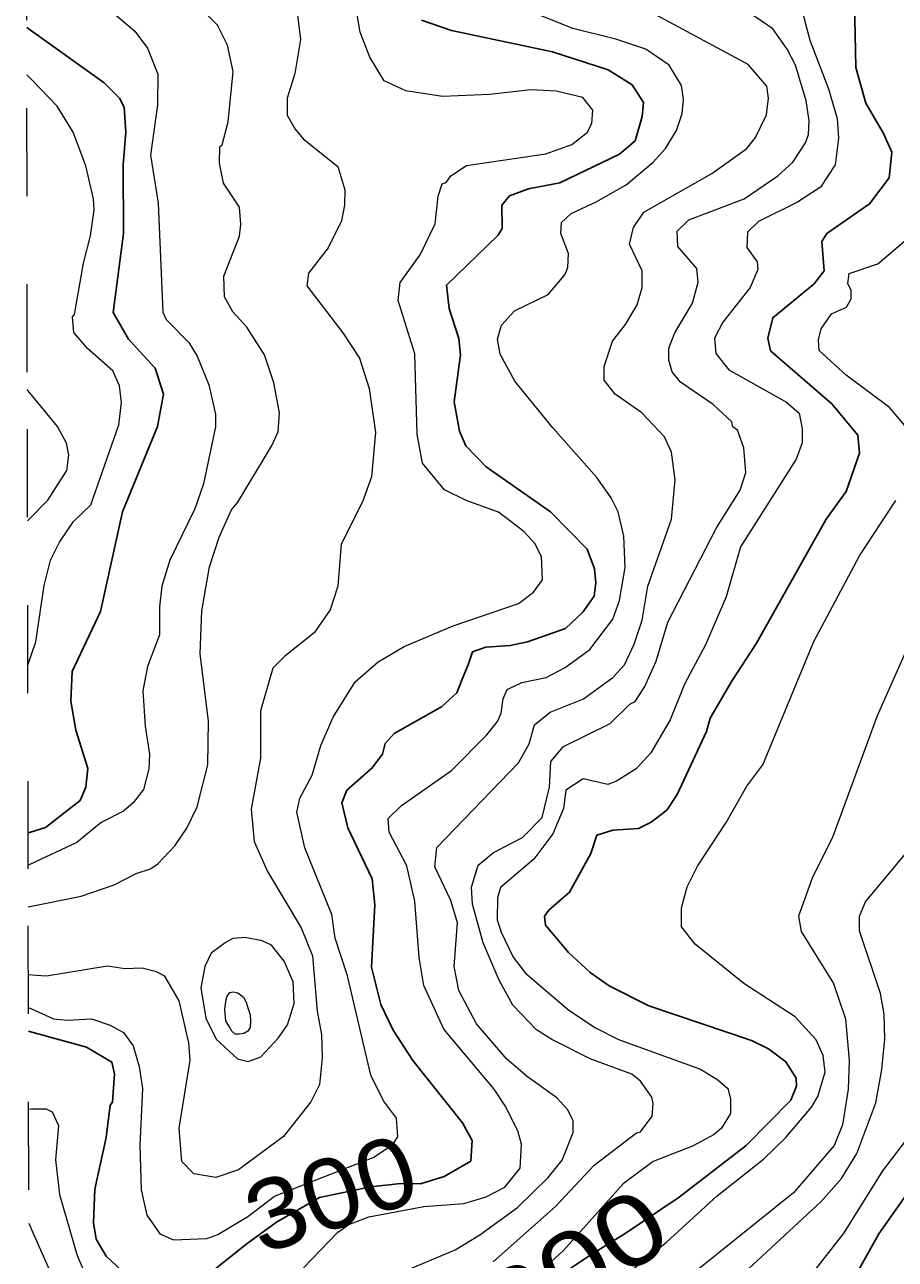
# Model space of a CAD drawing. Extents: x 474.5 to 500, y 7345.7 to 7373.4.
# Drawn here: x 474.558 to 475.548, y 7350.356 to 7351.759 of the extents above; entities that cross this region are included whole.
import ezdxf
from ezdxf.enums import TextEntityAlignment as Align

# ---------------------------------------------------------------- set-up
doc = ezdxf.new("R2010")
doc.units = 0
doc.header["$LTSCALE"] = 0.032
doc.linetypes.add('SHORT_DASHED', pattern=[2.7, 1.5, -1.2])
for name, color, linetype, lineweight in [('1', 7, 'Continuous', 25), ('2', 7, 'Continuous', 13), ('22', 7, 'SHORT_DASHED', 13)]:
    doc.layers.add(name, color=color, linetype=linetype, lineweight=lineweight)
doc.layers.add('61', color=7, linetype='Continuous')

msp = doc.modelspace()

# ---------------------------------------------------------------- linework, layer by layer
at = {"layer": '1'}
for points in [[(475.1618, 7350.334), (475.2, 7350.3596), (475.241, 7350.3853), (475.3024, 7350.4264), (475.3785, 7350.485), (475.4292, 7350.5366), (475.4356, 7350.5527), (475.4353, 7350.5617), (475.4236, 7350.5804), (475.404, 7350.595), (475.3847, 7350.6046), (475.2676, 7350.6438), (475.2227, 7350.6667), (475.2009, 7350.6819), (475.1765, 7350.7046), (475.1503, 7350.7357), (475.1493, 7350.746), (475.1541, 7350.7527), (475.1777, 7350.773), (475.2018, 7350.8171), (475.2085, 7350.8381), (475.2269, 7350.8437), (475.2561, 7350.8455), (475.2706, 7350.8527), (475.2881, 7350.8662), (475.2999, 7350.8841), (475.3334, 7350.9559), (475.3377, 7350.9708), (475.3624, 7351.0139), (475.3903, 7351.0561), (475.4696, 7351.1972), (475.4921, 7351.2287), (475.5074, 7351.272), (475.5055, 7351.2925), (475.476, 7351.3283), (475.4062, 7351.3885), (475.403, 7351.4028), (475.4086, 7351.426), (475.4559, 7351.4647), (475.467, 7351.4795), (475.4644, 7351.5126), (475.4701, 7351.5217), (475.5188, 7351.5554), (475.541, 7351.5853), (475.5441, 7351.6143), (475.5347, 7351.6356), (475.5144, 7351.6699), (475.503, 7351.7105), (475.5018, 7351.7845)], [(474.7741, 7350.3441), (474.8109, 7350.3737), (474.8446, 7350.3979), (474.8934, 7350.4259), (474.9513, 7350.4383), (474.9857, 7350.442), (475.008, 7350.4416), (475.035, 7350.45), (475.0655, 7350.4675), (475.067, 7350.4907), (475.0561, 7350.5108), (474.9994, 7350.5818), (474.9769, 7350.6163), (474.9632, 7350.6453), (474.9523, 7350.6878), (474.9562, 7350.7587), (474.9531, 7350.7883), (474.9257, 7350.8463), (474.9188, 7350.8747), (474.9243, 7350.8891), (474.953, 7350.9139), (474.965, 7350.9301), (474.9681, 7350.9423), (474.9784, 7350.9536), (475.0322, 7350.9837), (475.0493, 7350.9999), (475.0554, 7351.0152), (475.0623, 7351.0317), (475.0674, 7351.0464), (475.0823, 7351.0518), (475.1102, 7351.0535), (475.1299, 7351.0576), (475.173, 7351.073), (475.1929, 7351.0915), (475.2056, 7351.1097), (475.2074, 7351.1249), (475.206, 7351.1406), (475.1977, 7351.1629), (475.1559, 7351.2055), (475.0829, 7351.2568), (475.0598, 7351.2803), (475.0524, 7351.2973), (475.0464, 7351.3304), (475.0535, 7351.384), (475.0516, 7351.4026), (475.0407, 7351.4367), (475.0376, 7351.463), (475.096, 7351.5195), (475.1012, 7351.5274), (475.1006, 7351.5541), (475.1092, 7351.5646), (475.1309, 7351.5728), (475.1667, 7351.5794), (475.2346, 7351.6119), (475.2521, 7351.6273), (475.2601, 7351.6549), (475.2616, 7351.6709), (475.2489, 7351.6908), (475.2216, 7351.7077), (475.1583, 7351.7283), (475.0434, 7351.7527), (475.0094, 7351.7644)], [(474.562, 7350.8404), (474.5635, 7350.8409), (474.5818, 7350.8466), (474.6211, 7350.8772), (474.6275, 7350.8924), (474.6298, 7350.9136), (474.6164, 7350.9574), (474.6106, 7350.9901), (474.6122, 7351.0238), (474.6443, 7351.092), (474.6695, 7351.2053), (474.709, 7351.3026), (474.7159, 7351.3393), (474.7065, 7351.3686), (474.676, 7351.4016), (474.6587, 7351.4319), (474.6706, 7351.5218), (474.6699, 7351.5998), (474.673, 7351.6371), (474.6713, 7351.6656), (474.6658, 7351.6757), (474.6485, 7351.693), (474.5622, 7351.7548), (474.5604, 7351.7561)], [(474.5624, 7350.6151), (474.5637, 7350.6148), (474.6283, 7350.5971), (474.6571, 7350.5799), (474.6602, 7350.5668), (474.6579, 7350.5343), (474.6554, 7350.531), (474.6508, 7350.4941), (474.6378, 7350.4357), (474.6364, 7350.3974), (474.6394, 7350.3788), (474.6509, 7350.3592), (474.6683, 7350.343)], [(475.5073, 7350.3452), (475.5293, 7350.3847), (475.5985, 7350.4833)]]:
    msp.add_lwpolyline(points, dxfattribs=at)
at = {"layer": '2'}
for points in [[(474.5624, 7350.642), (474.5818, 7350.6333), (474.591, 7350.6292), (474.6068, 7350.6276), (474.634, 7350.629), (474.6552, 7350.6219), (474.6706, 7350.6137), (474.6814, 7350.5985), (474.6881, 7350.5751), (474.6921, 7350.55), (474.6889, 7350.4854), (474.6905, 7350.4347), (474.697, 7350.406), (474.7117, 7350.3846), (474.7273, 7350.3778), (474.7652, 7350.3793), (474.7778, 7350.3839), (474.8117, 7350.4046), (474.8421, 7350.4276), (474.9544, 7350.4714), (474.9768, 7350.4864), (474.9822, 7350.4952), (474.9808, 7350.5161), (474.966, 7350.5358), (474.9518, 7350.5651), (474.9252, 7350.678), (474.9112, 7350.721), (474.9074, 7350.7477), (474.8766, 7350.8237), (474.8677, 7350.8639), (474.8709, 7350.8801), (474.885, 7350.9062), (474.8947, 7350.94), (474.909, 7350.9719), (474.934, 7351.0122), (474.96, 7351.035), (474.9895, 7351.0525), (475.0453, 7351.076), (475.1195, 7351.1012), (475.1366, 7351.1142), (475.1469, 7351.1282), (475.1458, 7351.1546), (475.1383, 7351.1695), (475.1257, 7351.1832), (475.0969, 7351.2049), (475.0601, 7351.2184), (475.0354, 7351.2304), (475.0106, 7351.2607), (475.0044, 7351.2938), (475.0017, 7351.3851), (474.9826, 7351.4457), (474.9852, 7351.4661), (475.0079, 7351.4976), (475.0249, 7351.5327), (475.0281, 7351.5643), (475.0328, 7351.5782), (475.0373, 7351.58), (475.0425, 7351.5873), (475.0605, 7351.5992), (475.1507, 7351.6125), (475.1801, 7351.6229), (475.1978, 7351.6368), (475.2028, 7351.6469), (475.2043, 7351.6619), (475.1928, 7351.6766), (475.1623, 7351.6838), (475.1336, 7351.6853), (475.0868, 7351.6798), (475.0331, 7351.6775), (474.9915, 7351.6839), (474.9668, 7351.6955), (474.9505, 7351.7223), (474.9394, 7351.7507), (474.9331, 7351.7885)], [(475.4365, 7351.7967), (475.4507, 7351.7417), (475.472, 7351.6863), (475.4818, 7351.6524), (475.4836, 7351.6304), (475.4795, 7351.5999), (475.4629, 7351.5747), (475.437, 7351.5575), (475.3926, 7351.5353), (475.38, 7351.5233), (475.3791, 7351.5061), (475.3909, 7351.4898), (475.3916, 7351.4809), (475.383, 7351.4604), (475.352, 7351.4211), (475.3424, 7351.4029), (475.3438, 7351.3854), (475.3586, 7351.3667), (475.4245, 7351.3303), (475.4386, 7351.3177), (475.442, 7351.2997), (475.4421, 7351.2839), (475.4355, 7351.2654), (475.3722, 7351.1657), (475.3556, 7351.1087)], [(474.6581, 7351.7735), (474.6832, 7351.7517), (474.6977, 7351.7324), (474.7094, 7351.7029), (474.709, 7351.668), (474.701, 7351.611), (474.7097, 7351.5563), (474.715, 7351.4326), (474.7191, 7351.424), (474.7448, 7351.3981), (474.7542, 7351.3824), (474.7673, 7351.3497), (474.7752, 7351.3164), (474.7751, 7351.3021), (474.7616, 7351.2372), (474.7514, 7351.2088), (474.7231, 7351.1506), (474.7142, 7351.1211), (474.7114, 7351.0974), (474.7113, 7351.0657), (474.6978, 7351.0295), (474.6925, 7351.002), (474.6952, 7350.9619), (474.7002, 7350.93), (474.6994, 7350.9133), (474.6933, 7350.89), (474.6816, 7350.8746), (474.6705, 7350.8652), (474.645, 7350.8524), (474.6173, 7350.8295), (474.5638, 7350.8046), (474.5621, 7350.8038)], [(474.5622, 7350.7564), (474.6222, 7350.7687), (474.66, 7350.7814), (474.6849, 7350.7942), (474.7013, 7350.7996), (474.7096, 7350.8052), (474.7287, 7350.8259), (474.7423, 7350.8458), (474.7544, 7350.8703), (474.7665, 7350.9177), (474.7671, 7350.9676), (474.7576, 7351.0442), (474.7595, 7351.0929), (474.7684, 7351.1431), (474.7792, 7351.1766), (474.7932, 7351.2077), (474.8006, 7351.2163), (474.8389, 7351.28), (474.8462, 7351.2963), (474.8478, 7351.318), (474.8413, 7351.3521), (474.8308, 7351.384), (474.8106, 7351.4152), (474.7946, 7351.4327), (474.7853, 7351.45), (474.7847, 7351.4734), (474.8023, 7351.5187), (474.8039, 7351.5321), (474.8023, 7351.5518), (474.7842, 7351.5792), (474.7795, 7351.6017), (474.78, 7351.6204), (474.7825, 7351.6228), (474.7894, 7351.6486), (474.795, 7351.706), (474.7887, 7351.7361), (474.7775, 7351.7587), (474.7549, 7351.7812)], [(474.8677, 7351.776), (474.8716, 7351.7425), (474.8651, 7351.7039), (474.8564, 7351.6755), (474.8565, 7351.6564), (474.8655, 7351.6405), (474.8749, 7351.6294), (474.914, 7351.5981), (474.922, 7351.5714), (474.9219, 7351.5542), (474.9185, 7351.5364), (474.903, 7351.5055), (474.8808, 7351.4768), (474.8789, 7351.4622), (474.9197, 7351.409), (474.9389, 7351.38), (474.9498, 7351.3457), (474.9571, 7351.2957), (474.9523, 7351.2452), (474.9421, 7351.2168), (474.918, 7351.1686), (474.914, 7351.1208), (474.9053, 7351.0939), (474.8871, 7351.0681), (474.8539, 7351.0415), (474.8404, 7351.0276), (474.8262, 7350.9791), (474.8261, 7350.9253), (474.8157, 7350.8675), (474.8192, 7350.8306), (474.8341, 7350.7966), (474.8724, 7350.7327), (474.8852, 7350.7008), (474.8906, 7350.6379), (474.8956, 7350.6113), (474.8964, 7350.585), (474.8932, 7350.5546), (474.8835, 7350.5347), (474.8522, 7350.4955), (474.8012, 7350.4574), (474.7754, 7350.4488), (474.7506, 7350.4528), (474.7367, 7350.4669), (474.7337, 7350.5049), (474.7464, 7350.5823), (474.7449, 7350.6017), (474.7337, 7350.6496), (474.7175, 7350.6777), (474.7079, 7350.6826), (474.6916, 7350.6866), (474.6718, 7350.6858), (474.6522, 7350.6889), (474.583, 7350.6778), (474.571, 7350.6786), (474.5623, 7350.6792)], [(474.8752, 7350.3462), (474.9137, 7350.3863), (474.9265, 7350.3952), (474.9494, 7350.4041), (475.0121, 7350.4158), (475.0575, 7350.4193), (475.083, 7350.4269), (475.104, 7350.4378), (475.1213, 7350.4594), (475.1229, 7350.4865), (475.1188, 7350.5017), (475.1044, 7350.5304), (475.092, 7350.5491), (475.0347, 7350.6174), (475.0121, 7350.6671), (475.0065, 7350.6987), (475.0017, 7350.7629), (474.9928, 7350.8032), (474.9726, 7350.8415), (474.9714, 7350.8569), (474.9865, 7350.8718), (475.0433, 7350.9116), (475.0837, 7350.952), (475.0957, 7350.9671), (475.1, 7350.9766), (475.1023, 7350.9928), (475.1067, 7351.0036), (475.1232, 7351.0113), (475.1511, 7351.0173), (475.1725, 7351.0286), (475.2007, 7351.0491), (475.2269, 7351.0836), (475.2346, 7351.1045), (475.241, 7351.1423), (475.2395, 7351.1777), (475.2329, 7351.2053), (475.2249, 7351.2212), (475.2087, 7351.2445), (475.1587, 7351.3008), (475.1154, 7351.3539), (475.0986, 7351.3845), (475.0959, 7351.4016), (475.1001, 7351.4176), (475.1149, 7351.4339), (475.1532, 7351.4524), (475.1724, 7351.4748), (475.1756, 7351.4832), (475.1763, 7351.4991), (475.1678, 7351.522), (475.1686, 7351.5345), (475.1793, 7351.5447), (475.2078, 7351.5578), (475.2421, 7351.5773), (475.2728, 7351.603), (475.2866, 7351.6185), (475.2992, 7351.639), (475.3057, 7351.6584), (475.3073, 7351.6741), (475.305, 7351.6902), (475.291, 7351.7133), (475.2643, 7351.7314), (475.2301, 7351.7427), (475.1814, 7351.7549), (475.1106, 7351.7832)], [(474.997, 7350.3454), (475.0477, 7350.3665), (475.0758, 7350.3835), (475.1185, 7350.4148), (475.1534, 7350.4489), (475.1691, 7350.4685), (475.1819, 7350.4998), (475.1819, 7350.5131), (475.1758, 7350.5256), (475.163, 7350.5393), (475.1298, 7350.5632), (475.1065, 7350.5833), (475.072, 7350.6236), (475.0518, 7350.6612), (475.0464, 7350.6888), (475.0502, 7350.7381), (475.0427, 7350.7638), (475.0244, 7350.802), (475.0267, 7350.8239), (475.1197, 7350.9202), (475.1317, 7350.9418), (475.1376, 7350.9635), (475.1556, 7350.9777), (475.1934, 7350.993), (475.227, 7351.0172), (475.24, 7351.0317), (475.2512, 7351.0549), (475.2602, 7351.0825), (475.2666, 7351.1208), (475.2936, 7351.197), (475.2977, 7351.2417), (475.2937, 7351.2734), (475.2855, 7351.2906), (475.2598, 7351.3179), (475.2296, 7351.3392), (475.2169, 7351.3551), (475.217, 7351.3707), (475.2265, 7351.3995), (475.2412, 7351.4183), (475.2544, 7351.4409), (475.2601, 7351.4603), (475.2601, 7351.4794), (475.2459, 7351.5097), (475.2505, 7351.5288), (475.2622, 7351.5461), (475.3396, 7351.59), (475.3792, 7351.6184), (475.3892, 7351.6308), (475.4014, 7351.6568), (475.4037, 7351.6757), (475.402, 7351.6892), (475.3806, 7351.714), (475.2611, 7351.7785)], [(475.0908, 7350.3529), (475.1618, 7350.4158), (475.2057, 7350.4629), (475.2536, 7350.4996), (475.2585, 7350.5008), (475.2714, 7350.5186), (475.2728, 7350.5331), (475.2711, 7350.54), (475.2583, 7350.5582), (475.2485, 7350.5662), (475.2011, 7350.5836), (475.1574, 7350.6055), (475.1399, 7350.6168), (475.113, 7350.6445), (475.0977, 7350.6731), (475.0794, 7350.7157), (475.0672, 7350.7596), (475.0662, 7350.7788), (475.0738, 7350.8039), (475.0911, 7350.8181), (475.1243, 7350.8354), (475.1466, 7350.8579), (475.1549, 7350.8926), (475.1565, 7350.9218), (475.1709, 7350.9386), (475.224, 7350.9648), (475.2461, 7350.9868), (475.2523, 7350.99), (475.2632, 7351.007), (475.276, 7351.0357), (475.2894, 7351.0802), (475.3446, 7351.1873), (475.3718, 7351.23), (475.3782, 7351.25), (475.3759, 7351.2781), (475.3685, 7351.2983), (475.3633, 7351.3022), (475.3621, 7351.3079), (475.341, 7351.3276), (475.3038, 7351.3529), (475.2945, 7351.3647), (475.2907, 7351.3777), (475.2905, 7351.3916), (475.2975, 7351.4089), (475.3174, 7351.4425), (475.3239, 7351.4667), (475.3222, 7351.482), (475.3008, 7351.5069), (475.3001, 7351.5246), (475.3133, 7351.5372), (475.3761, 7351.5614), (475.4143, 7351.5873), (475.4315, 7351.6031), (475.4461, 7351.6249), (475.4493, 7351.6345), (475.4501, 7351.6502), (475.4468, 7351.6725), (475.4344, 7351.7132), (475.4252, 7351.7315), (475.4088, 7351.7544), (475.3821, 7351.7726)], [(474.5617, 7351.0311), (474.5632, 7351.0356), (474.5706, 7351.0576), (474.5804, 7351.1218), (474.5875, 7351.1506), (474.5977, 7351.171), (474.6135, 7351.1943), (474.6334, 7351.2136), (474.6651, 7351.3042), (474.6683, 7351.3299), (474.6658, 7351.3486), (474.6584, 7351.3656), (474.6297, 7351.3911), (474.6138, 7351.4095), (474.6124, 7351.4273), (474.6148, 7351.4297), (474.6248, 7351.4883), (474.6331, 7351.5191), (474.637, 7351.5487), (474.6362, 7351.5614), (474.6277, 7351.5986), (474.6134, 7351.6369), (474.5952, 7351.6666), (474.5654, 7351.6973), (474.5605, 7351.7023)], [(475.5606, 7351.3012), (475.5415, 7351.3241), (475.4921, 7351.3608), (475.4616, 7351.389), (475.4607, 7351.4009), (475.4639, 7351.4133), (475.4753, 7351.4305), (475.4924, 7351.4381), (475.4979, 7351.4477), (475.4978, 7351.4571), (475.494, 7351.4649), (475.4957, 7351.4763), (475.528, 7351.4873), (475.5614, 7351.5156)], [(474.5614, 7351.1952), (474.5633, 7351.1971), (474.5846, 7351.2188), (474.606, 7351.2524), (474.6084, 7351.2703), (474.6057, 7351.2837), (474.5955, 7351.3025), (474.5622, 7351.3431), (474.5611, 7351.3444)], [(475.2511, 7350.3456), (475.288, 7350.3754), (475.3453, 7350.4279), (475.3983, 7350.4697), (475.4236, 7350.4941), (475.4526, 7350.5288), (475.4599, 7350.5407), (475.4683, 7350.5684), (475.466, 7350.5874), (475.4579, 7350.6051), (475.434, 7350.6313), (475.3758, 7350.6695), (475.3204, 7350.714), (475.3049, 7350.7337), (475.3049, 7350.7554), (475.3113, 7350.7793), (475.323, 7350.8027), (475.3557, 7350.8522), (475.3791, 7350.8936), (475.3973, 7350.9178), (475.4555, 7351.058), (475.5074, 7351.1555), (475.5488, 7351.2184)], [(475.3556, 7351.1087), (475.3324, 7351.0544), (475.3083, 7351.0094), (475.2921, 7350.969), (475.2701, 7350.9317), (475.2533, 7350.9135), (475.2312, 7350.8994), (475.2213, 7350.8957), (475.1932, 7350.9018), (475.1735, 7350.8892), (475.1708, 7350.8684), (475.1587, 7350.8394), (475.137, 7350.8107), (475.0991, 7350.7783), (475.0959, 7350.7668), (475.0954, 7350.7415), (475.0997, 7350.7276), (475.1135, 7350.6992), (475.1277, 7350.6809), (475.1768, 7350.639), (475.2071, 7350.6191), (475.2333, 7350.6058), (475.3266, 7350.5719), (475.3461, 7350.5598), (475.3575, 7350.5498), (475.3606, 7350.5383), (475.3606, 7350.5216), (475.3505, 7350.5049), (475.3421, 7350.4975), (475.3174, 7350.4845), (475.2727, 7350.467), (475.2387, 7350.4416), (475.1708, 7350.3657), (475.1205, 7350.3197)], [(475.5591, 7351.045), (475.5273, 7350.9735), (475.4771, 7350.8365), (475.4534, 7350.7889), (475.4381, 7350.7458), (475.441, 7350.7285), (475.4778, 7350.6692), (475.4915, 7350.629), (475.4954, 7350.5818), (475.4946, 7350.5491), (475.488, 7350.5086), (475.4786, 7350.4852), (475.4324, 7350.4312), (475.3241, 7350.3445)], [(475.3654, 7350.3307), (475.4636, 7350.4217), (475.4867, 7350.4478), (475.5042, 7350.4759), (475.5259, 7350.5336), (475.5329, 7350.5716), (475.5361, 7350.6062), (475.5353, 7350.6344), (475.5313, 7350.6581), (475.5075, 7350.7291), (475.5075, 7350.7458), (475.5142, 7350.762), (475.5648, 7350.823)], [(474.5626, 7350.5266), (474.5658, 7350.5267), (474.5824, 7350.527), (474.5892, 7350.5236), (474.5964, 7350.5078), (474.5932, 7350.4689), (474.5977, 7350.4295), (474.6178, 7350.36), (474.6285, 7350.3355)], [(475.5703, 7350.5044), (475.5336, 7350.4565), (475.4896, 7350.386), (475.4304, 7350.31)], [(474.5628, 7350.3967), (474.5671, 7350.387), (474.5938, 7350.3265)]]:
    msp.add_lwpolyline(points, dxfattribs=at)
for points in [[(474.786, 7350.7154), (474.7702, 7350.7039), (474.7629, 7350.6887), (474.7584, 7350.6644), (474.7641, 7350.6301), (474.7757, 7350.6059), (474.8, 7350.5837), (474.8121, 7350.5805), (474.8267, 7350.5858), (474.8465, 7350.6072), (474.8569, 7350.6223), (474.8644, 7350.6466), (474.8635, 7350.6711), (474.8532, 7350.6946), (474.8387, 7350.7128), (474.8282, 7350.7177), (474.8089, 7350.7217), (474.7947, 7350.7206)], [(474.7856, 7350.6397), (474.787, 7350.6491), (474.7884, 7350.655), (474.7915, 7350.6591), (474.7951, 7350.66), (474.8006, 7350.6586), (474.8069, 7350.6537), (474.8101, 7350.6482), (474.8123, 7350.6406), (474.8146, 7350.6338), (474.815, 7350.6265), (474.8146, 7350.6193), (474.8119, 7350.6152), (474.8073, 7350.6125), (474.8024, 7350.6116), (474.7974, 7350.6116), (474.7938, 7350.6152), (474.7902, 7350.6211), (474.787, 7350.627)]]:
    msp.add_lwpolyline(points, close=True, dxfattribs=at)
at = {"layer": '22'}
msp.add_lwpolyline([(474.5711, 7345.7156), (474.5701, 7346.2805), (474.5691, 7346.8454), (474.5681, 7347.4103), (474.5671, 7347.9751), (474.5661, 7348.54), (474.5651, 7349.1049), (474.5641, 7349.6698), (474.5631, 7350.2347), (474.5621, 7350.7995), (474.5611, 7351.3644), (474.5601, 7351.9293), (474.5591, 7352.4942), (474.5581, 7353.059)], dxfattribs=at)

# ---------------------------------------------------------------- texts
at = {"layer": '61'}
for s, rotation, width, p in [('300', 19.179, 1.1, (474.9197, 7350.3928)), ('200', 32.714, 1.25, (475.2051, 7350.3143))]:
    msp.add_text(s, height=0.08, rotation=rotation, dxfattribs=dict(at, width=width)).set_placement(p, align=Align.CENTER)

doc.saveas('drawing.dxf')
